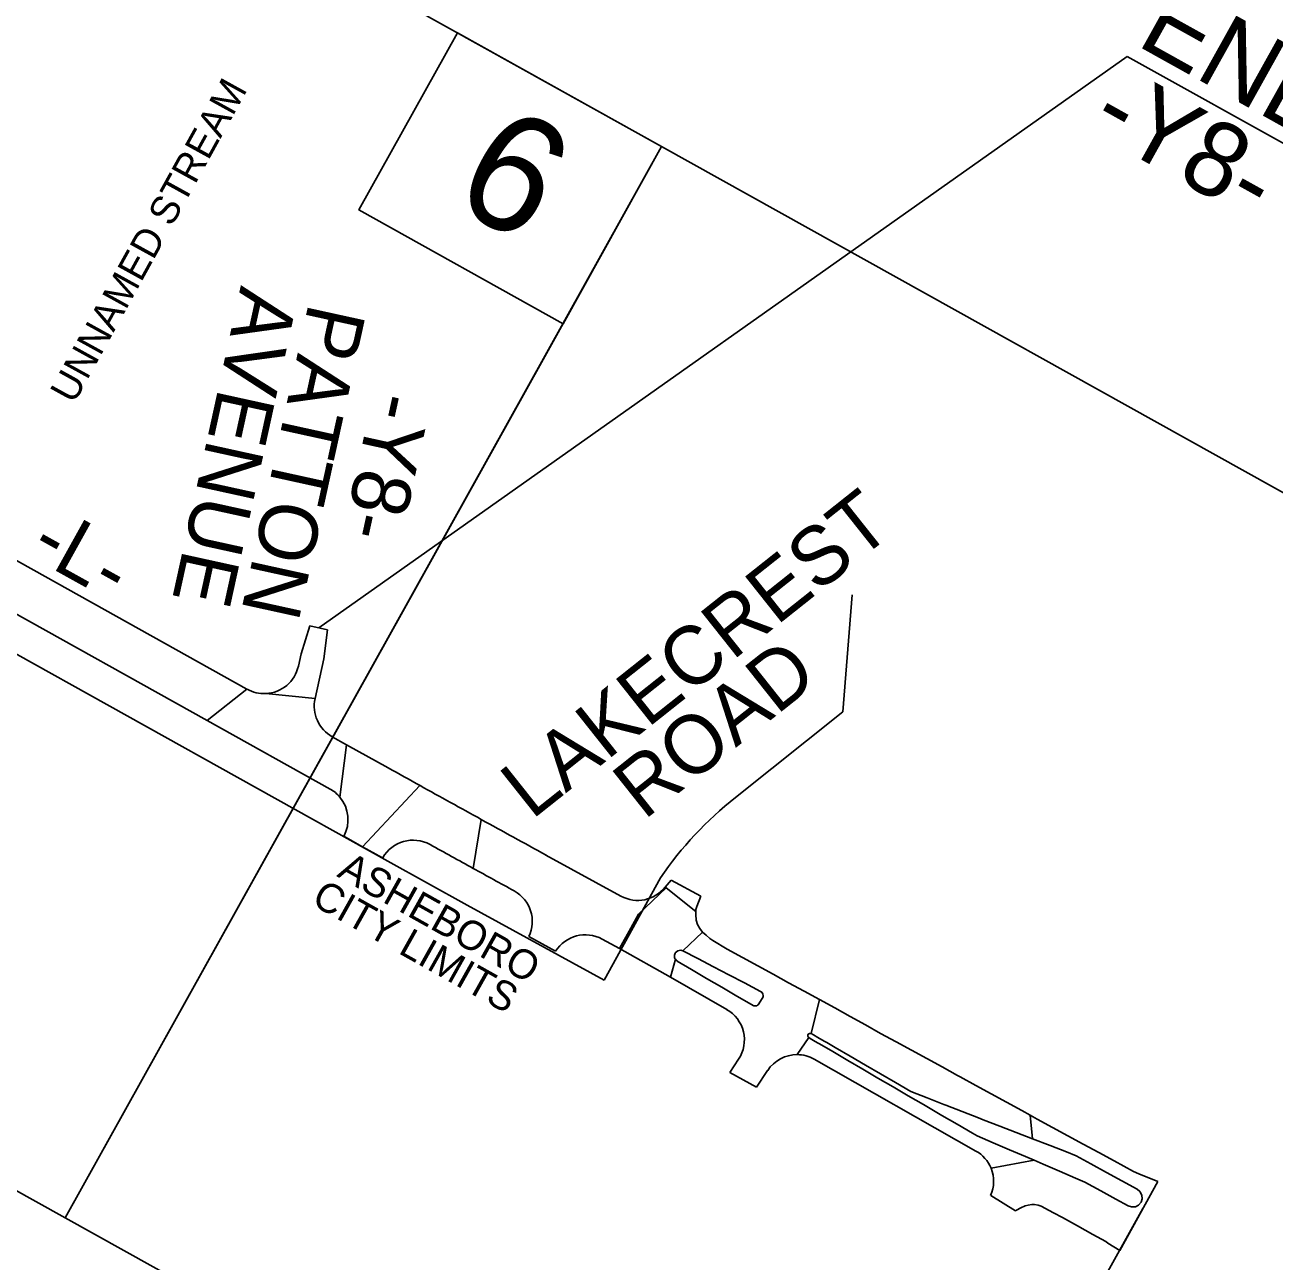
# Model space of a CAD drawing. Extents: x 1754939 to 1770240, y 706534 to 717510.
# Drawn here: x 1764816 to 1765886, y 710258 to 711317 of the extents above; entities that cross this region are included whole.
import ezdxf

# ---------------------------------------------------------------- set-up
doc = ezdxf.new("R2010")
doc.units = 0
for name, color, linetype in [('ENG SEALS CELL', 7, 'Continuous'), ('Prop Lane Arrow CELL', 7, 'Continuous'), ('Prop SS Cut Line', 7, 'Continuous'), ('Sheet PE Seal Cell', 7, 'Continuous')]:
    doc.layers.add(name, color=color, linetype=linetype)

msp = doc.modelspace()

# ---------------------------------------------------------------- linework, layer by layer
at = {"layer": 'ENG SEALS CELL'}
for points in [[(1763634.2, 710972.3), (1763634.2, 710972.3), (1763865.7, 711388), (1764374.3, 711762), (1765360.9, 711212.6), (1765258, 711027.8), (1764850.1, 710295.2)], [(1765360.9, 711212.6), (1765186.1, 711309.9), (1765101.7, 711158.3), (1765276.5, 711060.9)], [(1764850.1, 710295.2), (1764850.1, 710295.2), (1765360.9, 711212.6), (1765360.9, 711212.6), (1766611.7, 710516), (1766483.1, 710285.1), (1766100.9, 709598.7)]]:
    msp.add_lwpolyline(points, close=True, dxfattribs=at)
at = {"layer": 'Prop Lane Arrow CELL'}
for p, q in [((1765005.9, 710747.9), (1764575.4, 710988.1)), ((1764768.9, 710834.3), (1764971.7, 710721.2)), ((1765059.6, 710802.1), (1765052.2, 710778.1)), ((1765074.9, 710798.7), (1765059.6, 710802.1)), ((1765071.7, 710773.8), (1765074.9, 710798.7)), ((1765052.2, 710778.1), (1765049.9, 710767.7)), ((1765064.2, 710739.8), (1765071.7, 710773.8)), ((1764971.7, 710721.2), (1765005.9, 710747.9)), ((1764971.7, 710721.2), (1765005.9, 710747.9)), ((1765005.9, 710747.9), (1764971.7, 710721.2)), ((1765022, 710744.1), (1765064.2, 710739.8)), ((1765022, 710744.1), (1765064.2, 710739.8)), ((1765064.2, 710739.8), (1765022, 710744.1)), ((1764971.7, 710721.2), (1765077.1, 710662.4)), ((1765091.2, 710700.3), (1765078.9, 710707.2)), ((1765091.2, 710700.3), (1765085.5, 710655.4)), ((1765085.5, 710655.4), (1765091.2, 710700.3)), ((1765091.2, 710700.3), (1765085.5, 710655.4)), ((1765126.8, 710680.5), (1765091.2, 710700.3)), ((1765077.1, 710662.4), (1765077.1, 710662.4)), ((1765077.1, 710662.4), (1765077.1, 710662.4)), ((1765154, 710665.3), (1765104.9, 710612.9)), ((1765104.9, 710612.9), (1765154, 710665.3)), ((1765154, 710665.3), (1765104.9, 710612.9)), ((1765199.5, 710594.4), (1765206.4, 710636.3)), ((1765206.4, 710636.3), (1765199.5, 710594.4)), ((1765199.5, 710594.4), (1765206.4, 710636.3)), ((1765088.8, 710621.9), (1765104.9, 710612.9)), ((1765104.9, 710612.9), (1765122, 710603.4)), ((1765162.6, 710614.8), (1765162.6, 710614.8)), ((1765162.6, 710614.8), (1765162.6, 710614.8)), ((1765326, 710570.7), (1765261.9, 710605.8)), ((1765122, 710603.4), (1765122.1, 710603.5)), ((1765369.1, 710584.3), (1765364, 710578.4)), ((1765394.5, 710570.5), (1765369.1, 710584.3)), ((1765341.1, 710555.2), (1765364.8, 710577.7)), ((1765364.8, 710577.7), (1765341.1, 710555.2)), ((1765364.8, 710577.7), (1765364, 710578.4)), ((1765364, 710578.4), (1765364.8, 710577.7)), ((1765390.1, 710557.6), (1765364.8, 710577.7)), ((1765364.8, 710577.7), (1765390.1, 710557.6)), ((1765391, 710561.7), (1765394.5, 710570.5)), ((1765334.5, 710543.2), (1765341.1, 710555.2)), ((1765341.1, 710555.2), (1765334.5, 710543.2)), ((1765390.1, 710558.8), (1765390.2, 710559.3)), ((1765390.1, 710557.6), (1765390.1, 710558.8)), ((1765390.2, 710559.3), (1765391, 710561.7)), ((1765324.9, 710525.7), (1765334.5, 710543.2)), ((1765334.5, 710543.2), (1765324.9, 710525.7)), ((1765247.3, 710536), (1765270.2, 710523.4)), ((1765310.1, 710533.8), (1765324.9, 710525.7)), ((1765379.1, 710523.8), (1765396, 710539.7)), ((1765379.1, 710523.8), (1765396, 710539.7)), ((1765396, 710539.7), (1765379.1, 710523.8)), ((1765324.9, 710525.7), (1765368.6, 710501.3)), ((1765379, 710523.9), (1765379.1, 710523.8)), ((1765379.1, 710523.8), (1765392, 710517.1)), ((1765368.6, 710501.3), (1765372.7, 710516.6)), ((1765368.6, 710501.3), (1765372.7, 710516.6)), ((1765372.7, 710516.6), (1765368.6, 710501.3)), ((1765374.3, 710515), (1765374.1, 710515.2)), ((1765392, 710517.1), (1765405.3, 710510.2)), ((1765368.6, 710501.3), (1765416.7, 710473.6)), ((1765412.5, 710492.7), (1765399.5, 710500.2)), ((1765425.4, 710485.1), (1765412.5, 710492.7)), ((1765431.9, 710496.3), (1765445.7, 710489.1)), ((1765445.7, 710489.1), (1765447, 710488)), ((1765447, 710488), (1765447.6, 710486.7)), ((1765439.8, 710476.8), (1765425.4, 710485.1)), ((1765440.7, 710476.6), (1765439.8, 710476.8)), ((1765441.6, 710476.6), (1765440.7, 710476.6)), ((1765442.4, 710476.8), (1765441.6, 710476.6)), ((1765443.1, 710477.2), (1765442.4, 710476.8)), ((1765443.7, 710477.6), (1765443.1, 710477.2)), ((1765444.3, 710478.3), (1765443.7, 710477.6)), ((1765447.8, 710484.3), (1765444.3, 710478.3)), ((1765447.6, 710486.7), (1765447.8, 710485.5)), ((1765447.8, 710485.5), (1765447.8, 710484.3)), ((1765496, 710482.1), (1765489, 710453)), ((1765489, 710453), (1765496, 710482.1)), ((1765496, 710482.1), (1765489, 710453)), ((1765486.9, 710449.5), (1765477, 710434.9)), ((1765477, 710434.9), (1765486.9, 710449.5)), ((1765486.9, 710449.5), (1765477, 710434.9)), ((1765486.2, 710450.8), (1765486.1, 710451.5)), ((1765488, 710448.8), (1765486.9, 710449.5)), ((1765426.9, 710431), (1765419.4, 710419.7)), ((1765491.6, 710431), (1765630, 710352.3)), ((1765419.4, 710419.7), (1765442.3, 710407.1)), ((1765442.3, 710407.1), (1765451.7, 710421.4)), ((1765559.2, 710407.3), (1765546.2, 710414.8)), ((1765548.3, 710418.4), (1765561.2, 710410.9)), ((1765561.2, 710410.9), (1765574.2, 710403.3)), ((1765600.9, 710382.9), (1765598, 710384.6)), ((1765676.5, 710383), (1765678.4, 710362.8)), ((1765678.4, 710362.8), (1765676.5, 710383)), ((1765676.5, 710383), (1765678.4, 710362.8)), ((1765658.8, 710353.5), (1765644.7, 710359.5)), ((1765678.4, 710362.8), (1765693.5, 710357)), ((1765630.1, 710352.4), (1765630, 710352.3)), ((1765630, 710352.3), (1765630.1, 710352.4)), ((1765693.5, 710357), (1765707.5, 710351.6)), ((1765679.8, 710344.5), (1765643, 710337.6)), ((1765643, 710337.6), (1765679.8, 710344.5)), ((1765679.8, 710344.5), (1765643, 710337.6)), ((1765687.7, 710341.1), (1765679.8, 710344.5)), ((1765701.5, 710335.1), (1765687.7, 710341.1)), ((1765741.8, 710334), (1765754.9, 710326.8)), ((1765754.9, 710326.8), (1765768, 710319.6)), ((1765785.8, 710326.2), (1765769.5, 710332.8)), ((1765753.4, 710267.2), (1765785.8, 710326.2)), ((1765768, 710319.6), (1765770.5, 710317.7)), ((1765770.5, 710317.7), (1765772.2, 710314.5)), ((1765642.7, 710314.3), (1765664, 710301.2)), ((1765772.2, 710314.5), (1765772.5, 710311.5)), ((1765766.6, 710304.6), (1765763.4, 710304.5)), ((1765743, 710273.5), (1765753.4, 710267.2))]:
    msp.add_line(p, q, dxfattribs=at)
for points in [[(1765396, 710539.7), (1765393.6, 710542.8), (1765391.6, 710546.3), (1765390.4, 710550.2), (1765390.1, 710554.8), (1765390.1, 710557.6)], [(1765496, 710482.1), (1765482.9, 710489.3), (1765469.7, 710496.5), (1765456.5, 710503.8), (1765443.4, 710510.9), (1765430.2, 710518.1), (1765417, 710525.3), (1765404.7, 710532.7), (1765402.1, 710534.5), (1765399, 710537.1), (1765396, 710539.7)], [(1765399.5, 710500.2), (1765386.6, 710507.8), (1765374.3, 710515)], [(1765405.3, 710510.2), (1765418.6, 710503.2), (1765431.9, 710496.3)], [(1765614.3, 710417.1), (1765601.2, 710424.4), (1765588, 710431.6), (1765574.9, 710438.8), (1765561.7, 710446), (1765548.5, 710453.1), (1765535.5, 710460.4), (1765522.3, 710467.6), (1765509.2, 710474.9), (1765496, 710482.1)], [(1765486.1, 710451.5), (1765486.5, 710452.3), (1765487, 710452.8), (1765487.7, 710453.1)], [(1765486.9, 710449.5), (1765486.4, 710450.1), (1765486.2, 710450.8)], [(1765487.7, 710453.1), (1765488.4, 710453.1), (1765489, 710453)], [(1765507.4, 710437.5), (1765498, 710443), (1765492.5, 710446.2), (1765488, 710448.8)], [(1765489, 710453), (1765490.9, 710451.8), (1765494.6, 710449.7)], [(1765494.6, 710449.7), (1765500.1, 710446.5), (1765502.3, 710445.2), (1765509.4, 710441), (1765522.4, 710433.5)], [(1765546.2, 710414.8), (1765533.3, 710422.4), (1765520.3, 710429.9), (1765507.4, 710437.5)], [(1765522.4, 710433.5), (1765535.4, 710425.9), (1765548.3, 710418.4)], [(1765676.5, 710383), (1765669.4, 710387), (1765656.2, 710394.2), (1765643, 710401.3), (1765629.9, 710408.6), (1765616.7, 710415.8), (1765614.3, 710417.1)], [(1765598, 710384.6), (1765585.1, 710392.2), (1765572.1, 710399.7), (1765559.2, 710407.3)], [(1765574.2, 710403.3), (1765588.3, 710397.8), (1765602.5, 710392.3)], [(1765602.5, 710392.3), (1765604.4, 710391.5), (1765618.4, 710386.1)], [(1765644.7, 710359.5), (1765631, 710365.5), (1765627.1, 710367.7), (1765614, 710375.3), (1765600.9, 710382.9)], [(1765618.4, 710386.1), (1765632.4, 710380.7), (1765636.4, 710379.1)], [(1765769.5, 710332.8), (1765765.1, 710334.9), (1765748.4, 710343.9), (1765735.2, 710351.1), (1765722, 710358.2), (1765708.8, 710365.4), (1765695.7, 710372.6), (1765682.5, 710379.7), (1765676.5, 710383)], [(1765636.4, 710379.1), (1765650.4, 710373.7), (1765664.5, 710368.2), (1765678.4, 710362.8)], [(1765679.8, 710344.5), (1765672.6, 710347.6), (1765658.8, 710353.5)], [(1765707.5, 710351.6), (1765715.9, 710348.3), (1765728.6, 710341.3), (1765741.8, 710334)], [(1765750, 710311.2), (1765736.9, 710318.4), (1765723.3, 710325.7), (1765715.3, 710329.2), (1765701.5, 710335.1)], [(1765664, 710301.2), (1765664.8, 710301.7), (1765668.5, 710303.8), (1765672.3, 710305.3), (1765674.9, 710306.1), (1765678, 710306.5), (1765680.3, 710306.5), (1765683.3, 710305.9), (1765685.8, 710305), (1765692.8, 710301.4), (1765696.4, 710299.5), (1765704.1, 710295.3), (1765717, 710288.2), (1765730.2, 710281), (1765741.2, 710274.9), (1765743, 710273.5)], [(1765763.4, 710304.5), (1765760.3, 710305.5), (1765750, 710311.2)], [(1765772.5, 710311.5), (1765771.6, 710308.6), (1765769.3, 710305.9), (1765766.6, 710304.6)]]:
    msp.add_lwpolyline(points, dxfattribs=at)
for centre, radius, start, end in [((1765020.6, 710774.1), 30, 272.7694, 347.6289), ((1765020.6, 710774.1), 30, 240.8436, 272.7694), ((1765093.5, 710733.4), 30, 167.6289, 240.8436), ((1774861, 728128.9), 19980, 240.8436, 240.9329), ((1765062.4, 710636.2), 30, 39.8378, 60.8436), ((1774861, 728128.9), 19980, 240.9329, 241.10465), ((1765062.4, 710636.2), 30, 331.42, 39.8378), ((1774861, 728128.9), 19980, 241.10465, 241.28635), ((1765148.1, 710588.6), 30, 61.0232, 150.1188), ((1774861, 728128.9), 20020, 241.02466, 241.14538), ((1774861, 728128.9), 20020, 241.14538, 241.25992), ((1765220.2, 710548.8), 30, 334.6341, 61.2599), ((1765340.5, 710597), 30, 241.2864, 321.7034), ((1765295.6, 710507.5), 30, 61.2864, 147.9345), ((1765376.9, 710519.3), 5, 148.1021, 170.601), ((1765376.9, 710519.3), 5, 170.601, 172.1148), ((1765376.9, 710519.3), 5, 172.1148, 213.1402), ((1765376.9, 710519.3), 5, 147.6727, 148.1021), ((1765376.9, 710519.3), 5, 84.3217, 147.6727), ((1765376.9, 710519.3), 5, 83.9636, 84.3217), ((1765376.9, 710519.3), 5, 65.1198, 83.9636), ((1765376.9, 710519.3), 5, 213.1402, 236.7007), ((1765401.8, 710447.5), 30, 326.6444, 60.3918), ((1765476.8, 710404.9), 30, 89.5529, 146.6444), ((1765476.8, 710404.9), 30, 60.3918, 89.5529), ((1765615.2, 710326.3), 30, 22.0661, 60.3494), ((1765615.2, 710326.3), 30, 336.3971, 22.0661)]:
    msp.add_arc(centre, radius, start, end, dxfattribs=at)
at = {"layer": 'Prop SS Cut Line'}
for p, q in [((1765067.3, 710800.4), (1765759.5, 711289.8)), ((1765759.5, 711289.8), (1766608.3, 710817.1)), ((1765773, 710303), (1765386.7, 709610.9))]:
    msp.add_line(p, q, dxfattribs=at)
at = {"layer": 'Sheet PE Seal Cell'}
for p, q in [((1764563.7, 710914.5), (1765126.4, 710600.5)), ((1765516.1, 710728.4), (1765524.2, 710828.8)), ((1765424.2, 710655.2), (1765516.1, 710728.4)), ((1765311.8, 710498.6), (1765359.9, 710586.3))]:
    msp.add_line(p, q, dxfattribs=at)
msp.add_lwpolyline([(1765126.4, 710600.5), (1765194.4, 710562.9), (1765311.8, 710498.6)], dxfattribs=at)
msp.add_arc((1765623.4, 710404.8), 320, 128.4945, 145.4348, dxfattribs=at)

# ---------------------------------------------------------------- texts
at = {"layer": 'ENG SEALS CELL'}
msp.add_text('6', height=100, rotation=330.8875, dxfattribs=at).set_placement((1765178.5, 711164.4))
at = {"layer": 'Prop SS Cut Line'}
for s, p in [('END CONSTRUCTION', (1765766.2, 711300.1)), ('-Y8- POT Sta. 11+00.00', (1765725.5, 711227.1))]:
    msp.add_text(s, height=63.75, rotation=330.8875, dxfattribs=at).set_placement(p)
at = {"layer": 'Sheet PE Seal Cell'}
for s, height, rotation, p in [('UNNAMED STREAM', 24.3, 61.1112, (1764857.6, 710991.4)), ('AVENUE', 50, 257.6289, (1765000.7, 711094.1)), ('PATTON ', 50, 257.6289, (1765059, 711079.9)), ('-Y8-', 50, 257.6289, (1765114.9, 711004.6)), ('LAKECREST ', 50, 38.4363, (1765249.7, 710635.5)), ('-L-', 50, 330.9544, (1764818, 710862.7)), ('ROAD', 50, 38.4363, (1765345.8, 710635.2)), ('ASHEBORO ', 25, 330.7501, (1765082.1, 710587.9)), ('CITY LIMITS', 25, 330.7501, (1765060, 710564))]:
    msp.add_text(s, height=height, rotation=rotation, dxfattribs=at).set_placement(p)

doc.saveas('drawing.dxf')
